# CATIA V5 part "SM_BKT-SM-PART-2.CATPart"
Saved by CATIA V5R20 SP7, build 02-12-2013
Part number: SM_BKT
Bounding box of the stored display mesh (mm): x 0 to 139.973, y -20 to 228.383, z 0 to 41
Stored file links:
  C:\Users\CAS-\Desktop\Exercise Files\SM_BKT-SM-PART-2.CATPart
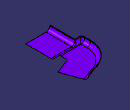
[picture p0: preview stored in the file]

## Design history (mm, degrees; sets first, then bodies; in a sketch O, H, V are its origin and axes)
Set1 "CONST_GEO"
  Point1: type OnCurve, Support Sketch1, Length 10
Set2 "Inputs"
  Sketch1 "Flange Sketch" on xy-plane, origin (0, 0, 0), H (1, 0, 0), V (0, 1, 0)
    point P1 (0, -20)
    line L1 (0, -20) -> (0, 125)
    arc A1 centre (90, 125) radius 90 from (0, 125) to (59.2182, 209.5723) cw
    point P3 (90, 125)
    line L2 (59.2182, 209.5723) -> (120.2982, 231.8036)
    radius A1 = 90
    distance H P3 = 125
    angle L1 L2 = 110
    length L2 = 65
    distance H P1 = 20
    coincidence: P1 V
    vertical: L1 V
    tangency: A1 L1, A1 L2
  Sketch2 "Main Body Sketch" on yz-plane, origin (0, 0, 0), H (0, 1, 0), V (0, 0, 1)
    point P1 (-20, 0)
    line L1 (-20, 0) -> (75, 0)
    point P2 (75, 0)
    line L2 (75, 0) -> (100, 25)
    line L3 (100, 25) -> (275, 25)
    reference intersected line E1 through (0, 0) direction (0, 1) from zx-plane
    distance V P1 = 20
    angle L1 L2 = 45
    distance L1 L3 = 25
    distance E1 P2 = 75
    length L3 = 175
    horizontal: L1 H, L3 H
    coincidence: H L1
Set3 "Spliting Elements"
  Plane1: type Normal, Curve Sketch1, RefPoint Point1
  Offset1: Offset Extrude2, Length 85
  Extract1: ExtractElem edge [face of Fillet3 | face of Extrude2 from Sketch1.L2]
  Extract2: ExtractElem edge [face of Fillet3 | face of Extrude2 from Sketch1.L1]
  Join1: Elements (Extract2; Extract1)
  CurvePar1: Offset Join1, Offset2 0, Offset1 3, Support Extrude2
Set4 "Split"
  Split1: ToCut Fillet3, Cutting (CurvePar1; Plane1; Offset1)
Set5 "Operations"
  Extrude1 "Slab-1": Element1 Sketch2, Lim1 209, Lim2 87
  Extrude2 "Slab-2": Element1 Sketch1, Lim1 209, Lim2 87
  Fillet1: radius 13, on edge [face of Extrude1 from Sketch2.L2 | face of Extrude1 from Sketch2.L1]
  Fillet2: radius 10, on edge [face of Extrude1 from Sketch2.L3 | face of Extrude1 from Sketch2.L2]
  Fillet3 "Main-Body": type BiTangent, Element1 Extrude2, Element2 Fillet2, Radius 13
Body1 (main body)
